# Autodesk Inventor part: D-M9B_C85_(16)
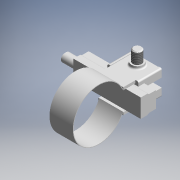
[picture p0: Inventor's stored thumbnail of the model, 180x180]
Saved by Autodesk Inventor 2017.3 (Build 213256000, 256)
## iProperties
Part Number: D-M9B_C85_(16)
Material: Generic
Catalog Web Link: www.cadenas.de
Description: C85/CD85 SW-ISO Standard Air Cylinder:Standard Type Double Acting Single Rod
Vendor: SMC
Document SubType Name: Modeling
Designer: partserver
Manufacturer: SMC
Mass: 1.40986 g
Surface Area: 22.9985 cm^2
Volume: 1.40986 cm^3
Density: 1 g/cm^3
Appearance: PSOLRGB-255-255-255
Category: PARTsolutions
Company: SMC
Title: D-M9B_C85
Author: Cadenas PARTsolutions
Comments: ISO Standard Air Cylinder:Standard Type Double Acting Single Rod
PSOL_IDENT_0: {$CADENAS_DATA\23d-libs\smc_jp\actuator\standard_air_cylinder\c85\c85\parts\c85_sw_band.prj},174 {VT
PSOL_IDENT_1: YP=3D},{NB=D-M9B_C85_(16)},{LINA=D-M9B_C85},{NN=C85/CD85 SW},{DATE=09.12.2020 02:57:06},{GEOMDATE=03
PSOL_IDENT_2: .08.2017 08:12:00},{VERSION=},{LINEID=40},{WBVAR=AUTOSW},{WBNUMERIC=}  {NB=D-M9B_C85_(16)},{LINA=D-M
PSOL_IDENT_3: 9B_C85},{KT=DUMMY},{BORE=16.000},{AUTOSW=-M9B},{ASN=A},{SWITCHS=F},{HS=11.1},{ORDER=D-M9B_C85},{D1=1
PSOL_IDENT_4: 7.400}
NB: D-M9B_C85_(16)
NN: C85/CD85 SW
NT: ISO Standard Air Cylinder:Standard Type Double Acting Single Rod
NBSYN: $ORDER._($BORE.)
LINA: D-M9B_C85
CATALOG: SMC (JP
BORE: 16
AUTOSW: M9B
D1: 17.4
SUPPLIER: SMC
ARTICLENO: D-M9B_C85_(16)
BOMINFO: D-M9B_C85
CREATOR: CADENAS GmbH
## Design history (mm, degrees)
sketch "Sketch_14"
  geometry: L1 (3, 1.5)-(6, 1.5); L2 (6.5, 1)-(6.5, -1); L3 (6, -1.5)-(3, -1.5); L4 (3, -1.5)-(3, -3.75); L5 (3.5, -4.25)-(4, -4.25); L6 (4, -4.25)-(4, -3.25); L7 (4, -3.25)-(12.6, -3.25); L8 (12.6, -3.25)-(12.6, -4.25); L9 (12.6, -4.25)-(13.1, -4.25); L10 (13.6, -3.75)-(13.6, -1.5); L11 (13.6, -1.5)-(10.6, -1.5); L12 (10.1, -1)-(10.1, 1); L13 (10.6, 1.5)-(13.6, 1.5); L14 (13.6, 1.5)-(13.6, 3.75); L15 (13.1, 4.25)-(12.6, 4.25); L16 (12.6, 4.25)-(12.6, 3.25); L17 (12.6, 3.25)-(4, 3.25); L18 (4, 3.25)-(4, 4.25); L19 (4, 4.25)-(3.5, 4.25); L20 (3, 3.75)-(3, 1.5); A1 r 0.5 centre (6, 1) between (6.5, 1) and (6, 1.5); A2 r 0.5 centre (6, -1) between (6, -1.5) and (6.5, -1); A3 r 0.5 centre (3.5, -3.75) between (3, -3.75) and (3.5, -4.25); A4 r 0.5 centre (13.1, -3.75) between (13.1, -4.25) and (13.6, -3.75); A5 r 0.5 centre (10.6, -1) between (10.1, -1) and (10.6, -1.5); A6 r 0.5 centre (10.6, 1) between (10.6, 1.5) and (10.1, 1); A7 r 0.5 centre (13.1, 3.75) between (13.6, 3.75) and (13.1, 4.25); A8 r 0.5 centre (3.5, 3.75) between (3.5, 4.25) and (3, 3.75)
  constraints: 40 end point, 16 point on circle, 8 centre point
extrude "Extrusion1" join sketch "Sketch_14" distance "d0" = 8; taper "d1" = 0 deg
sketch "Sketch_13"
  geometry: L1 (1.4, 2.8)-(1.4, -2.8); L2 (1.4, -2.8)-(2.9, -2.8); L3 (2.9, -2.8)-(2.9, -1.7); L4 (2.9, -1.7)-(3.4, -1.7); L5 (3.4, -1.7)-(3.4, 1.7); L6 (3.4, 1.7)-(2.9, 1.7); L7 (2.9, 1.7)-(2.9, 2.8); L8 (2.9, 2.8)-(1.4, 2.8)
  constraints: 16 end point
extrude "Extrusion2" cut sketch "Sketch_13" distance "d2" = 20; taper "d3" = 0 deg
sketch "Sketch_12"
  geometry: L1 (-3.175, -2.3)-(3.175, -2.3); L2 (3.175, -2.3)-(3.175, -0.01); L3 (2.775, 0.79)-(2.775, 2.9); L4 (2.775, 2.9)-(-2.775, 2.9); L5 (-2.775, 2.9)-(-2.775, 0.79); L6 (-3.175, -0.01)-(-3.175, -2.3); A1 r 1 centre (3.775, 0.79) between (2.775, 0.79) and (3.175, -0.01); A2 r 1 centre (-3.775, 0.79) between (-3.175, -0.01) and (-2.775, 0.79)
  constraints: 12 end point, 4 point on circle, 2 centre point
extrude "Extrusion3" join sketch "Sketch_12" distance "d4" = 23; taper "d5" = 0 deg
sketch "Sketch_8"
  geometry: L1 (1.323, -1.5)-(3.1, -1.5); L2 (3.1, -1.5)-(3.1, 1.5); L3 (3.1, 1.5)-(1.323, 1.5); A1 r 2 centre (0, 0) between (1.323, 1.5) and (1.323, -1.5)
  constraints: 6 end point, 2 point on circle, 1 centre point
extrude "Extrusion4" cut sketch "Sketch_8" distance "d6" = 22; taper "d7" = 0 deg
sketch "Sketch_19"
  geometry: L1 (1.428, -1.4)-(2.6, -1.4); L2 (2.6, -1.4)-(2.6, 1.4); L3 (2.6, 1.4)-(1.428, 1.4); A1 r 2 centre (0, 0) between (1.428, 1.4) and (1.428, -1.4)
  constraints: 6 end point, 2 point on circle, 1 centre point
extrude "Extrusion5" join sketch "Sketch_19" distance "d8" = 22; taper "d9" = 0 deg
sketch "Sketch_5"
  geometry: C1 r 1.2 at (2, 0); C2 r 1 at (2, 0); 2 further points
  constraints: 2 centre point
extrude "Extrusion6" cut sketch "Sketch_5" stored distance "d10" = 2; taper "d11" = 0 deg
sketch "Sketch_6"
  geometry: L1 (1.492, -0.861)-(2.861, 0.508); L2 (2.508, 0.861)-(1.139, -0.508); A1 r 1 centre (2, 0) between (1.139, -0.508) and (1.492, -0.861); A2 r 1 centre (2, 0) between (2.861, 0.508) and (2.508, 0.861)
  constraints: 4 end point, 4 point on circle, 2 centre point
extrude "Extrusion7" cut sketch "Sketch_6" stored distance "d12" = 1; taper "d13" = 0 deg
sketch "Sketch_26"
  geometry: L1 (8.15, 0.5)-(8.15, -0.5); L2 (8.4, -0.75)-(10.6, -0.75); L3 (10.85, -0.5)-(10.85, 0.5); L4 (10.6, 0.75)-(8.4, 0.75); A1 r 0.25 centre (8.4, -0.5) between (8.15, -0.5) and (8.4, -0.75); A2 r 0.25 centre (10.6, -0.5) between (10.6, -0.75) and (10.85, -0.5); A3 r 0.25 centre (10.6, 0.5) between (10.85, 0.5) and (10.6, 0.75); A4 r 0.25 centre (8.4, 0.5) between (8.4, 0.75) and (8.15, 0.5)
  constraints: 8 end point, 8 point on circle, 4 centre point
extrude "Extrusion8" cut sketch "Sketch_26" stored distance "d14" = 0.2; taper "d15" = 0 deg
sketch "Sketch_21"
  geometry: L1 (0.25, 1.35)-(-0.25, 1.35); L2 (-0.25, -1.35)-(0.25, -1.35); A1 r 1.35 centre (-0.25, 0) between (-0.25, 1.35) and (-0.25, -1.35); A2 r 1.35 centre (0.25, 0) between (0.25, -1.35) and (0.25, 1.35)
  constraints: 4 end point, 4 point on circle, 2 centre point
extrude "Extrusion9" join sketch "Sketch_21" distance "d16" = 27; taper "d17" = 0 deg
sketch "Sketch_7"
  geometry: L1 (3.45, -3.096)-(3.45, 8.8); L2 (3.45, 8.8)-(3.25, 8.8); L3 (3.25, 8.8)-(3.25, -3.23); L4 (-3.175, -3.2)-(-3.175, 8.8); L5 (-3.175, 8.8)-(-3.375, 8.8); L6 (-3.375, 8.8)-(-3.375, -3.065); A1 r 8.9 centre (0, -11.3) between (-3.375, -3.065) and (3.45, -3.096); A2 r 8.7 centre (0, -11.3) between (-3.175, -3.2) and (3.25, -3.23)
  constraints: 12 end point, 4 point on circle, 2 centre point
extrude "Extrusion10" join sketch "Sketch_7" stored distance "d18" = 8; taper "d19" = 0 deg
sketch "Sketch_15"
  geometry: L1 (3.25, 8.8)-(3.25, -3.23); L2 (3.25, -3.23)-(4.15, -3.23); L3 (4.15, -3.23)-(4.15, 8.8); L4 (4.15, 8.8)-(3.25, 8.8)
  constraints: 8 end point
extrude "Extrusion11" join sketch "Sketch_15" stored distance "d20" = 8.5; taper "d21" = 0 deg
sketch "Sketch_16"
  geometry: L1 (-4.15, 8.8)-(-4.15, -3.23); L2 (-4.15, -3.23)-(-3.25, -3.23); L3 (-3.25, -3.23)-(-3.25, 8.8); L4 (-3.25, 8.8)-(-4.15, 8.8)
  constraints: 8 end point
extrude "Extrusion12" join sketch "Sketch_16" stored distance "d22" = 8.5; taper "d23" = 0 deg
sketch "Sketch_17"
  geometry: L1 (9.05, 5.8)-(-7.45, 5.8); L2 (-7.45, 5.8)-(-7.45, 6.55); L3 (-5.45, 8.55)-(-4.15, 8.55); L4 (-4.15, 8.55)-(-4.15, 7.3); L5 (-4.15, 7.3)-(4.15, 7.3); L6 (4.15, 7.3)-(4.15, 8.3); L7 (4.65, 7.8)-(5.15, 7.8); L8 (5.15, 7.8)-(5.15, 7.3); L9 (5.15, 7.3)-(8.743, 7.3); L10 (8.743, 7.3)-(9.05, 6.994); L11 (9.05, 6.994)-(9.05, 5.8); L12 (9.05, 5.8)-(-7.45, 5.8); A1 r 2 centre (-5.45, 6.55) between (-5.45, 8.55) and (-7.45, 6.55); A2 r 0.5 centre (4.65, 8.3) between (4.15, 8.3) and (4.65, 7.8)
  constraints: 24 end point, 4 point on circle, 2 centre point
revolve "Revolution1" sketch "Sketch_17" stored, may be unused: angle "d24" = 360 deg
thread "Thread1" dims "d25" = 3.5935, "d26" = 0
sketch "Sketch_18"
  geometry: L1 (-2, 0.343)-(-2, -0.343); L2 (-2, -0.343)-(-1.342, -0.343); L3 (-0.343, -1.342)-(-0.343, -2); L4 (-0.343, -2)-(0.343, -2); L5 (0.343, -2)-(0.343, -1.342); L6 (1.342, -0.343)-(2, -0.343); L7 (2, -0.343)-(2, 0.343); L8 (2, 0.343)-(1.342, 0.343); L9 (0.343, 1.342)-(0.343, 2); L10 (0.343, 2)-(-0.343, 2); L11 (-0.343, 2)-(-0.343, 1.342); L12 (-1.342, 0.343)-(-2, 0.343); A1 r 1 centre (-1.343, -1.343) between (-0.343, -1.342) and (-1.342, -0.343); A2 r 1 centre (1.343, -1.343) between (1.342, -0.343) and (0.343, -1.342); A3 r 1 centre (1.343, 1.343) between (0.343, 1.342) and (1.342, 0.343); A4 r 1 centre (-1.343, 1.343) between (-1.342, 0.343) and (-0.343, 1.342)
  constraints: 24 end point, 8 point on circle, 4 centre point
extrude "Extrusion13" cut sketch "Sketch_18" distance "d27" = 1.5; taper "d28" = 0 deg
node "SW_XY"
node "SW_YZ"
node "SW_ZX"
node "SW_X"
node "SW_Y"
node "SW_Z"
node "SW_Center"
body "Solid1"
